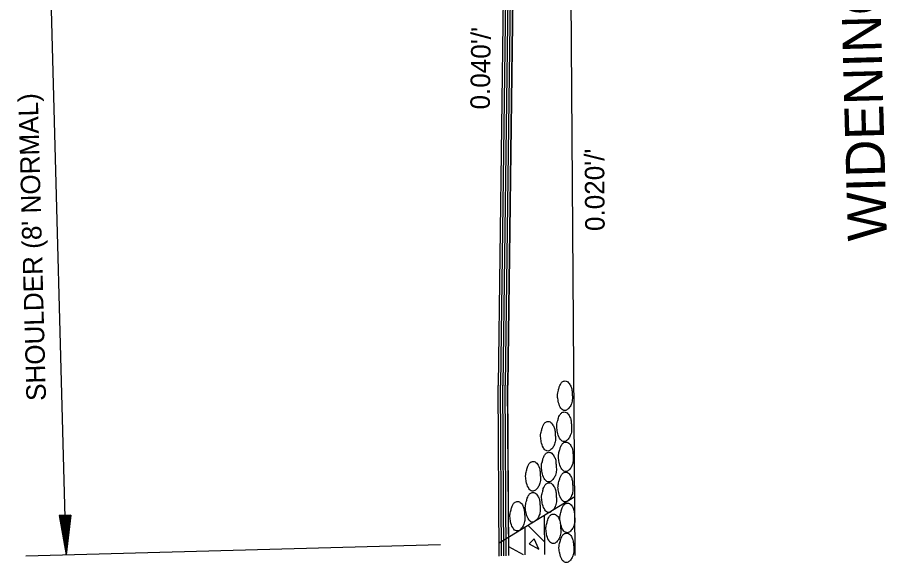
# Model space of a CAD drawing. Extents: x 1929624 to 1935547, y 596315 to 605721.
# Drawn here: x 1931762.6 to 1932029.9, y 600418.2 to 600586 of the extents above; entities that cross this region are included whole.
import ezdxf

# ---------------------------------------------------------------- set-up
doc = ezdxf.new("R2010")
doc.units = 0
doc.layers.add('Default', color=7, linetype='Continuous')

msp = doc.modelspace()

# ---------------------------------------------------------------- linework, layer by layer
at = {"layer": 'Default'}
for p, q in [((1931934.09, 600420.4), (1931931.39, 600809)), ((1931777.56, 600420.59), (1931768.8, 600746.92)), ((1931912.31, 600618.68), (1931910.39, 600472.78)), ((1931913.04, 600618.7), (1931911.12, 600472.8)), ((1931913.77, 600618.67), (1931911.85, 600472.77)), ((1931914.5, 600618.69), (1931912.58, 600472.79)), ((1931915.23, 600618.66), (1931913.31, 600472.76)), ((1931915.32, 600618.66), (1931913.4, 600472.86)), ((1931910.76, 600420.26), (1931910.39, 600472.78)), ((1931911.48, 600420.28), (1931911.12, 600472.8)), ((1931912.21, 600420.32), (1931911.85, 600472.82)), ((1931912.94, 600420.36), (1931912.58, 600472.84)), ((1931913.67, 600420.41), (1931913.31, 600472.81)), ((1931913.77, 600420.41), (1931913.4, 600472.86)), ((1931933.97, 600438.45), (1931910.73, 600424.17)), ((1931779.08, 600432.81), (1931775.41, 600432.71)), ((1931775.41, 600432.71), (1931777.56, 600420.59)), ((1931775.73, 600432.72), (1931777.5, 600422.63)), ((1931776.04, 600432.73), (1931777.45, 600424.72)), ((1931776.33, 600432.74), (1931777.39, 600426.76)), ((1931776.65, 600432.75), (1931777.34, 600428.8)), ((1931776.97, 600432.76), (1931777.28, 600430.84)), ((1931777.52, 600432.77), (1931777.28, 600430.84)), ((1931777.84, 600432.78), (1931777.34, 600428.8)), ((1931778.16, 600432.79), (1931777.39, 600426.76)), ((1931778.45, 600432.8), (1931777.45, 600424.72)), ((1931778.76, 600432.8), (1931777.5, 600422.63)), ((1931779.08, 600432.81), (1931777.56, 600420.59)), ((1931924.74, 600420.7), (1931924.66, 600432.73)), ((1931918.77, 600420.67), (1931918.71, 600429.07)), ((1931924.71, 600424.64), (1931919.69, 600429.68)), ((1931892.72, 600423.69), (1931765.22, 600420.26)), ((1931918.18, 600420.63), (1931913.72, 600423.13))]:
    msp.add_line(p, q, dxfattribs=at)
msp.add_lwpolyline([(1931922.93, 600422.37), (1931921.54, 600425.54), (1931920.02, 600424.04), (1931922.93, 600422.37)], dxfattribs=at)
for points in [[(1931928.68, 600469.49), (1931928.92, 600467.89), (1931929.55, 600466.06), (1931930.4, 600465.16), (1931930.94, 600465.03), (1931931.9, 600465.49), (1931932.42, 600466.04), (1931932.97, 600467.13), (1931933.27, 600468.69), (1931933.25, 600469.47), (1931933.17, 600470.68), (1931932.99, 600471.99), (1931932.47, 600473.05), (1931931.62, 600474), (1931930.99, 600474.12), (1931930.12, 600473.81), (1931929.56, 600473.06), (1931929.23, 600472.33), (1931928.97, 600471.25), (1931928.75, 600470.52), (1931928.68, 600469.49)], [(1931928.43, 600459.96), (1931928.67, 600458.36), (1931929.3, 600456.53), (1931930.15, 600455.63), (1931930.69, 600455.5), (1931931.65, 600455.96), (1931932.17, 600456.51), (1931932.73, 600457.59), (1931933.02, 600459.16), (1931933, 600459.93), (1931932.92, 600461.15), (1931932.74, 600462.45), (1931932.23, 600463.51), (1931931.37, 600464.46), (1931930.74, 600464.59), (1931929.87, 600464.27), (1931929.31, 600463.53), (1931928.99, 600462.79), (1931928.73, 600461.71), (1931928.5, 600460.98), (1931928.43, 600459.96)], [(1931923.46, 600457.02), (1931923.7, 600455.42), (1931924.33, 600453.59), (1931925.18, 600452.69), (1931925.72, 600452.56), (1931926.68, 600453.02), (1931927.2, 600453.57), (1931927.76, 600454.66), (1931928.05, 600456.22), (1931928.03, 600457), (1931927.95, 600458.21), (1931927.77, 600459.52), (1931927.26, 600460.57), (1931926.41, 600461.52), (1931925.77, 600461.65), (1931924.9, 600461.34), (1931924.34, 600460.59), (1931924.02, 600459.85), (1931923.76, 600458.78), (1931923.53, 600458.04), (1931923.46, 600457.02)], [(1931928.94, 600450.71), (1931929.18, 600449.11), (1931929.81, 600447.28), (1931930.66, 600446.38), (1931931.25, 600446.25), (1931932.21, 600446.71), (1931932.68, 600447.26), (1931933.23, 600448.34), (1931933.53, 600449.91), (1931933.51, 600450.69), (1931933.43, 600451.9), (1931933.25, 600453.21), (1931932.78, 600454.26), (1931931.88, 600455.21), (1931931.29, 600455.34), (1931930.43, 600455.03), (1931929.86, 600454.28), (1931929.54, 600453.54), (1931929.23, 600452.47), (1931929.06, 600451.73), (1931928.94, 600450.71)], [(1931923.73, 600447.56), (1931923.97, 600445.96), (1931924.6, 600444.13), (1931925.45, 600443.18), (1931925.99, 600443.05), (1931926.95, 600443.52), (1931927.47, 600444.07), (1931928.03, 600445.15), (1931928.33, 600446.71), (1931928.3, 600447.54), (1931928.22, 600448.75), (1931928.04, 600450.06), (1931927.53, 600451.07), (1931926.68, 600452.07), (1931926.04, 600452.19), (1931925.17, 600451.88), (1931924.61, 600451.14), (1931924.29, 600450.4), (1931924.03, 600449.27), (1931923.8, 600448.59), (1931923.73, 600447.56)], [(1931918.85, 600444.75), (1931919.09, 600443.15), (1931919.72, 600441.32), (1931920.57, 600440.37), (1931921.16, 600440.24), (1931922.12, 600440.7), (1931922.59, 600441.25), (1931923.14, 600442.34), (1931923.44, 600443.9), (1931923.42, 600444.73), (1931923.34, 600445.94), (1931923.16, 600447.25), (1931922.69, 600448.26), (1931921.79, 600449.25), (1931921.2, 600449.38), (1931920.34, 600449.07), (1931919.77, 600448.32), (1931919.45, 600447.59), (1931919.14, 600446.46), (1931918.97, 600445.77), (1931918.85, 600444.75)], [(1931928.83, 600441.42), (1931929.07, 600439.82), (1931929.7, 600437.99), (1931930.55, 600437.09), (1931931.14, 600436.96), (1931932.1, 600437.42), (1931932.57, 600437.97), (1931933.13, 600439.06), (1931933.42, 600440.62), (1931933.4, 600441.4), (1931933.32, 600442.61), (1931933.14, 600443.92), (1931932.68, 600444.97), (1931931.77, 600445.92), (1931931.19, 600446.05), (1931930.32, 600445.74), (1931929.76, 600444.99), (1931929.44, 600444.26), (1931929.13, 600443.18), (1931928.95, 600442.44), (1931928.83, 600441.42)], [(1931923.77, 600438.16), (1931924, 600436.57), (1931924.64, 600434.74), (1931925.49, 600433.79), (1931926.03, 600433.65), (1931926.99, 600434.12), (1931927.51, 600434.67), (1931928.06, 600435.75), (1931928.36, 600437.32), (1931928.34, 600438.14), (1931928.26, 600439.35), (1931928.08, 600440.66), (1931927.56, 600441.67), (1931926.71, 600442.67), (1931926.07, 600442.8), (1931925.21, 600442.48), (1931924.64, 600441.74), (1931924.32, 600441), (1931924.06, 600439.87), (1931923.84, 600439.19), (1931923.77, 600438.16)], [(1931918.79, 600435.2), (1931919.03, 600433.6), (1931919.66, 600431.77), (1931920.51, 600430.82), (1931921.1, 600430.69), (1931922.06, 600431.16), (1931922.53, 600431.71), (1931923.08, 600432.79), (1931923.38, 600434.35), (1931923.36, 600435.18), (1931923.28, 600436.39), (1931923.1, 600437.7), (1931922.63, 600438.71), (1931921.73, 600439.71), (1931921.14, 600439.84), (1931920.28, 600439.52), (1931919.71, 600438.78), (1931919.39, 600438.04), (1931919.08, 600436.91), (1931918.91, 600436.23), (1931918.79, 600435.2)], [(1931914.03, 600432.43), (1931914.27, 600430.84), (1931914.9, 600429), (1931915.76, 600428.1), (1931916.34, 600427.97), (1931917.3, 600428.44), (1931917.77, 600428.98), (1931918.33, 600430.07), (1931918.63, 600431.63), (1931918.61, 600432.41), (1931918.52, 600433.62), (1931918.34, 600434.93), (1931917.88, 600435.99), (1931916.98, 600436.94), (1931916.39, 600437.07), (1931915.52, 600436.75), (1931914.96, 600436.01), (1931914.64, 600435.27), (1931914.33, 600434.19), (1931914.15, 600433.46), (1931914.03, 600432.43)], [(1931929.4, 600431.91), (1931929.64, 600430.31), (1931930.27, 600428.48), (1931931.12, 600427.58), (1931931.71, 600427.45), (1931932.67, 600427.91), (1931933.14, 600428.46), (1931933.7, 600429.54), (1931934, 600431.11), (1931933.97, 600431.88), (1931933.89, 600433.1), (1931933.71, 600434.4), (1931933.25, 600435.46), (1931932.35, 600436.41), (1931931.76, 600436.54), (1931930.89, 600436.22), (1931930.33, 600435.48), (1931930.01, 600434.74), (1931929.7, 600433.66), (1931929.52, 600432.93), (1931929.4, 600431.91)], [(1931925.1, 600428.55), (1931925.34, 600426.95), (1931925.97, 600425.12), (1931926.82, 600424.22), (1931927.41, 600424.09), (1931928.37, 600424.55), (1931928.84, 600425.1), (1931929.4, 600426.19), (1931929.69, 600427.75), (1931929.67, 600428.53), (1931929.59, 600429.74), (1931929.41, 600431.05), (1931928.94, 600432.1), (1931928.04, 600433.05), (1931927.46, 600433.18), (1931926.59, 600432.87), (1931926.03, 600432.12), (1931925.71, 600431.39), (1931925.4, 600430.31), (1931925.22, 600429.57), (1931925.1, 600428.55)], [(1931929.12, 600422.7), (1931929.36, 600421.1), (1931929.99, 600419.27), (1931930.85, 600418.37), (1931931.43, 600418.24), (1931932.39, 600418.71), (1931932.86, 600419.25), (1931933.42, 600420.34), (1931933.72, 600421.9), (1931933.7, 600422.68), (1931933.61, 600423.89), (1931933.43, 600425.2), (1931932.97, 600426.26), (1931932.07, 600427.2), (1931931.48, 600427.33), (1931930.61, 600427.02), (1931930.05, 600426.28), (1931929.73, 600425.54), (1931929.42, 600424.46), (1931929.24, 600423.73), (1931929.12, 600422.7)]]:
    msp.add_spline(points, degree=3, dxfattribs=at)

# ---------------------------------------------------------------- texts
for s, height, rotation, p in [('WIDENING FOR GUARDRAIL', 12, 91.5377, (1932029.97, 600517.34)), ("0.040'/'", 6, 89.2471, (1931907.86, 600557.62)), ("SHOULDER (8' NORMAL)", 6, 91.5377, (1931771.42, 600468.06)), ("0.020'/'", 6, 90.3914, (1931943.2, 600520.28))]:
    msp.add_text(s, height=height, rotation=rotation, dxfattribs=at).set_placement(p)

doc.saveas('drawing.dxf')
